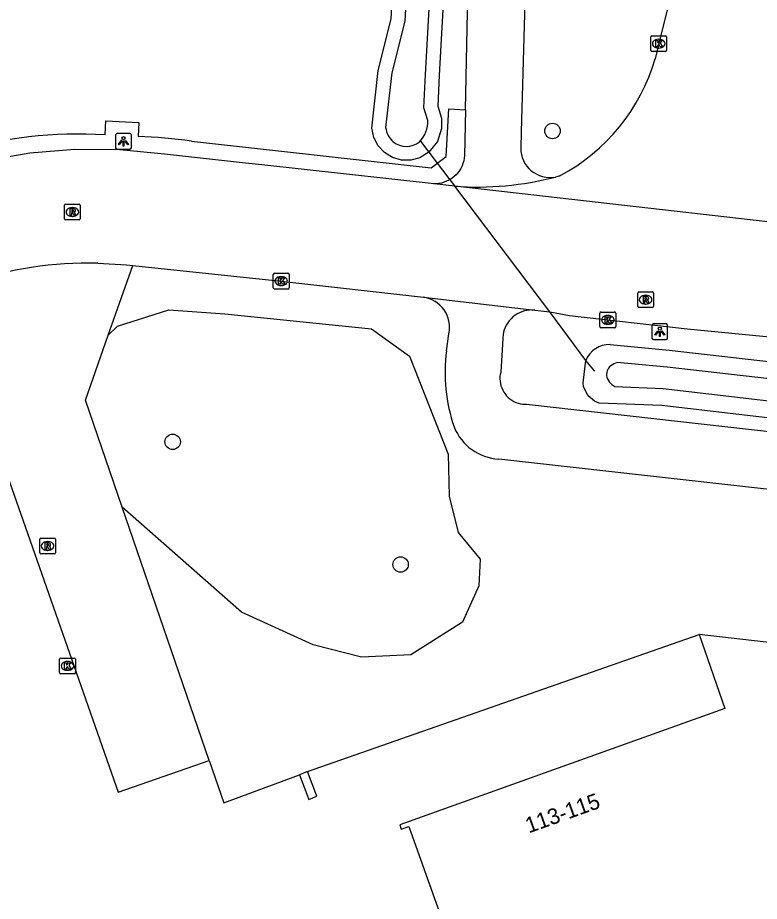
# Model space of a CAD drawing. Extents: x 161389 to 162585, y 388479 to 389761.
# Drawn here: x 162157.9 to 162205, y 388650.1 to 388706.2 of the extents above; entities that cross this region are included whole.
import ezdxf

# ---------------------------------------------------------------- set-up
doc = ezdxf.new("R2010")
doc.units = 0
for name, color, linetype in [('IMGEO_Berm_groen', 7, 'Continuous'), ('IMGEO_Boom', 7, 'Continuous'), ('IMGEO_Duiker', 7, 'Continuous'), ('IMGEO_Fietspad_gesloten', 7, 'Continuous'), ('IMGEO_Groenvoorziening', 7, 'Continuous'), ('IMGEO_Kolk', 7, 'Continuous'), ('IMGEO_Lichtpunt', 7, 'Continuous'), ('IMGEO_Pand', 7, 'Continuous'), ('IMGEO_Pand_nummerreeks', 7, 'Continuous'), ('IMGEO_Rijbaan_lokaal_gesloten', 7, 'Continuous'), ('IMGEO_Rijbaan_lokaal_open', 7, 'Continuous'), ('IMGEO_Rioolput', 7, 'Continuous'), ('IMGEO_Voetpad_open', 7, 'Continuous'), ('IMGEO_Waterloop', 7, 'Continuous')]:
    doc.layers.add(name, color=color, linetype=linetype)

msp = doc.modelspace()

# ---------------------------------------------------------------- linework, layer by layer
at = {"layer": 'IMGEO_Berm_groen'}
for points in [[(162195.511, 388685.399), (162199.258, 388685.044), (162309.372, 388672.493), (162313.677, 388672.019)], [(162314.929, 388670.455), (162314.838, 388669.228), (162314.739, 388669.003), (162314.316, 388668.451), (162313.561, 388668.026), (162313.044, 388667.945), (162308.893, 388668.677), (162198.797, 388681.534), (162194.824, 388681.685), (162194.516, 388681.817), (162194.124, 388682.146), (162193.837, 388682.714), (162193.797, 388682.968), (162193.974, 388684.393)]]:
    msp.add_lwpolyline(points, dxfattribs=at)
msp.add_arc((162195.451, 388683.814), 1.587, 87.8319, 158.5793, dxfattribs=at)
at = {"layer": 'IMGEO_Boom'}
for centre in [(162191.857, 388698.963), (162167.736, 388679.227), (162182.211, 388671.44)]:
    msp.add_circle(centre, 0.489, dxfattribs=at)
at = {"layer": 'IMGEO_Duiker'}
for points in [[(162183.486, 388698.312), (162184.011, 388697.62), (162185.337, 388695.87), (162185.651, 388695.455)], [(162194.552, 388683.711), (162193.974, 388684.393), (162191.691, 388687.487), (162185.651, 388695.455)]]:
    msp.add_lwpolyline(points, dxfattribs=at)
at = {"layer": 'IMGEO_Fietspad_gesloten'}
for points in [[(162186.329, 388700.295), (162186.802, 388723.126), (162187.239, 388731.997), (162188.536, 388741.532), (162190.109, 388750), (162191.97, 388758.076), (162195.928, 388774.095), (162196.55, 388776.78), (162196.93, 388779.509), (162197.064, 388782.261), (162196.952, 388785.015)], [(162190.386, 388722.102), (162190.347, 388716.013), (162190.335, 388715.366), (162189.876, 388698.902), (162189.839, 388697.876)], [(162186.329, 388700.295), (162186.269, 388697.407), (162186.252, 388697.229), (162186.22, 388697.063), (162186.173, 388696.9), (162186.112, 388696.742), (162186.037, 388696.59), (162185.949, 388696.446), (162185.848, 388696.31), (162185.736, 388696.183), (162185.612, 388696.067), (162185.479, 388695.962), (162185.337, 388695.87), (162185.285, 388695.84), (162185.134, 388695.766), (162184.976, 388695.705), (162184.814, 388695.659), (162184.649, 388695.627), (162184.481, 388695.61), (162184.312, 388695.609), (162184.144, 388695.622)], [(162190.731, 388687.591), (162190.565, 388687.6), (162190.4, 388687.594), (162190.235, 388687.573), (162190.073, 388687.537), (162189.915, 388687.488), (162189.762, 388687.424), (162189.615, 388687.347), (162189.476, 388687.257), (162189.345, 388687.155), (162189.224, 388687.041), (162189.113, 388686.918), (162189.014, 388686.785), (162188.927, 388686.643), (162188.854, 388686.495), (162188.794, 388686.34), (162188.747, 388686.181), (162188.716, 388686.018), (162188.699, 388685.853), (162188.696, 388685.79), (162188.57, 388683.655), (162188.54, 388683.511), (162188.523, 388683.366), (162188.52, 388683.219), (162188.529, 388683.073), (162188.552, 388682.928), (162188.587, 388682.786), (162188.635, 388682.647), (162188.695, 388682.513), (162188.766, 388682.385), (162188.849, 388682.265), (162188.943, 388682.151), (162189.046, 388682.047), (162189.158, 388681.953), (162189.278, 388681.868), (162189.405, 388681.795), (162189.538, 388681.734), (162189.676, 388681.684), (162189.818, 388681.647), (162189.962, 388681.623), (162190.109, 388681.612), (162190.209, 388681.612), (162327.081, 388666.21)], [(162185.128, 388685.009), (162185.28, 388686.094)], [(162212.05, 388675.493), (162188.441, 388678.131)]]:
    msp.add_lwpolyline(points, dxfattribs=at)
for centre, radius, start, end in [((162191.706, 388697.876), 1.867, 180.0152, 280.4452), ((162183.403, 388686.501), 1.92, 347.749, 82.4112), ((162195.589, 388683.618), 10.553, 172.4281, 199.0682), ((162188.627, 388681.366), 3.241, 201.6437, 266.7077)]:
    msp.add_arc(centre, radius, start, end, dxfattribs=at)
at = {"layer": 'IMGEO_Groenvoorziening'}
for points in [[(162185.324, 388714.25), (162184.667, 388702.506), (162184.568, 388700.542), (162184.809, 388699.772), (162184.811, 388699.122), (162184.547, 388698.299), (162184.011, 388697.62), (162183.444, 388697.26), (162182.868, 388697.109), (162182.272, 388697.116), (162181.7, 388697.28), (162181.192, 388697.59), (162180.784, 388698.024), (162180.506, 388698.551), (162180.377, 388699.132), (162180.783, 388702.801), (162181.617, 388706.073), (162182.042, 388714.232)], [(162163.648, 388686.001), (162164.223, 388686.562), (162167.504, 388687.618), (162171.048, 388687.354), (162180.363, 388686.411), (162182.776, 388684.676), (162185.228, 388678.454), (162185.303, 388675.776), (162185.869, 388673.476), (162187.264, 388671.779), (162187.189, 388670.082), (162186.133, 388667.782), (162182.852, 388665.708), (162179.722, 388665.557), (162176.667, 388666.349), (162172.104, 388668.423), (162164.533, 388675.08)], [(162176.301, 388658.294), (162201.171, 388666.993)], [(162170.064, 388658.999), (162170.991, 388656.301), (162175.785, 388658.097)]]:
    msp.add_lwpolyline(points, dxfattribs=at)
at = {"layer": 'IMGEO_Kolk'}
for p, q in [((162198.102, 388704.08), (162198.102, 388704.932)), ((162198.177, 388705.006), (162199.029, 388705.006)), ((162198.59, 388704.786), (162198.615, 388704.786)), ((162199.103, 388704.932), (162199.103, 388704.08)), ((162198.613, 388704.226), (162198.588, 388704.226)), ((162199.029, 388704.006), (162198.177, 388704.006)), ((162174.129, 388689.004), (162174.129, 388689.856)), ((162174.204, 388689.93), (162175.056, 388689.93)), ((162174.617, 388689.71), (162174.642, 388689.71)), ((162175.13, 388689.856), (162175.13, 388689.004)), ((162174.64, 388689.15), (162174.615, 388689.15)), ((162175.056, 388688.93), (162174.204, 388688.93)), ((162194.873, 388686.544), (162194.873, 388687.396)), ((162194.948, 388687.47), (162195.8, 388687.47)), ((162195.874, 388687.396), (162195.874, 388686.544)), ((162195.361, 388687.25), (162195.386, 388687.25)), ((162195.8, 388686.47), (162194.948, 388686.47)), ((162195.384, 388686.69), (162195.359, 388686.69)), ((162160.631, 388665.503), (162161.483, 388665.503)), ((162160.556, 388664.577), (162160.556, 388665.429)), ((162161.044, 388665.283), (162161.069, 388665.283)), ((162161.557, 388665.429), (162161.557, 388664.577)), ((162161.483, 388664.503), (162160.631, 388664.503)), ((162161.067, 388664.723), (162161.042, 388664.723))]:
    msp.add_line(p, q, dxfattribs=at)
for points in [[(162198.102, 388704.08), (162198.102, 388704.932)], [(162198.177, 388705.006), (162199.029, 388705.006)], [(162199.103, 388704.932), (162199.103, 388704.08)], [(162198.423, 388704.706), (162198.546, 388704.706), (162198.546, 388704.555), (162198.676, 388704.706), (162198.84, 388704.706), (162198.694, 388704.555), (162198.847, 388704.306), (162198.695, 388704.306), (162198.61, 388704.47), (162198.546, 388704.403), (162198.546, 388704.306), (162198.423, 388704.306), (162198.423, 388704.706)], [(162199.029, 388704.006), (162198.177, 388704.006)], [(162174.129, 388689.004), (162174.129, 388689.856)], [(162174.204, 388689.93), (162175.056, 388689.93)], [(162174.45, 388689.63), (162174.573, 388689.63), (162174.573, 388689.479), (162174.703, 388689.63), (162174.867, 388689.63), (162174.721, 388689.479), (162174.874, 388689.23), (162174.722, 388689.23), (162174.637, 388689.394), (162174.573, 388689.327), (162174.573, 388689.23), (162174.45, 388689.23), (162174.45, 388689.63)], [(162175.13, 388689.856), (162175.13, 388689.004)], [(162175.056, 388688.93), (162174.204, 388688.93)], [(162194.873, 388686.544), (162194.873, 388687.396)], [(162194.948, 388687.47), (162195.8, 388687.47)], [(162195.874, 388687.396), (162195.874, 388686.544)], [(162195.194, 388687.17), (162195.317, 388687.17), (162195.317, 388687.019), (162195.447, 388687.17), (162195.611, 388687.17), (162195.465, 388687.019), (162195.618, 388686.77), (162195.466, 388686.77), (162195.381, 388686.934), (162195.317, 388686.867), (162195.317, 388686.77), (162195.194, 388686.77), (162195.194, 388687.17)], [(162195.8, 388686.47), (162194.948, 388686.47)], [(162160.631, 388665.503), (162161.483, 388665.503)], [(162160.556, 388664.577), (162160.556, 388665.429)], [(162160.877, 388665.203), (162161, 388665.203), (162161, 388665.052), (162161.13, 388665.203), (162161.294, 388665.203), (162161.148, 388665.052), (162161.301, 388664.803), (162161.149, 388664.803), (162161.064, 388664.967), (162161, 388664.9), (162161, 388664.803), (162160.877, 388664.803), (162160.877, 388665.203)], [(162161.557, 388665.429), (162161.557, 388664.577)], [(162161.483, 388664.503), (162160.631, 388664.503)]]:
    msp.add_lwpolyline(points, dxfattribs=at)
for centre, start, end in [((162198.179, 388704.93), 91.552, 178.448), ((162198.179, 388704.93), 91.552, 178.448), ((162199.027, 388704.93), 1.552, 88.448), ((162199.027, 388704.93), 1.552, 88.448), ((162198.179, 388704.082), 181.552, 268.448), ((162198.179, 388704.082), 181.552, 268.448), ((162199.027, 388704.082), 271.552, 358.448), ((162199.027, 388704.082), 271.552, 358.448), ((162174.206, 388689.854), 91.552, 178.448), ((162174.206, 388689.854), 91.552, 178.448), ((162175.054, 388689.854), 1.552, 88.448), ((162175.054, 388689.854), 1.552, 88.448), ((162174.206, 388689.006), 181.552, 268.448), ((162174.206, 388689.006), 181.552, 268.448), ((162175.054, 388689.006), 271.552, 358.448), ((162175.054, 388689.006), 271.552, 358.448), ((162194.95, 388687.394), 91.552, 178.448), ((162194.95, 388687.394), 91.552, 178.448), ((162195.798, 388687.394), 1.552, 88.448), ((162195.798, 388687.394), 1.552, 88.448), ((162194.95, 388686.546), 181.552, 268.448), ((162194.95, 388686.546), 181.552, 268.448), ((162195.798, 388686.546), 271.552, 358.448), ((162195.798, 388686.546), 271.552, 358.448), ((162160.633, 388665.427), 91.552, 178.448), ((162160.633, 388665.427), 91.552, 178.448), ((162161.481, 388665.427), 1.552, 88.448), ((162161.481, 388665.427), 1.552, 88.448), ((162160.633, 388664.579), 181.552, 268.448), ((162160.633, 388664.579), 181.552, 268.448), ((162161.481, 388664.579), 271.552, 358.448), ((162161.481, 388664.579), 271.552, 358.448)]:
    msp.add_arc(centre, 0.0765, start, end, dxfattribs=at)
for centre, major_axis, ratio, start_param, end_param in [((162198.589, 388704.506), (-0.387, 0.002), 0.722429, 4.712389, 7.853982), ((162198.614, 388704.506), (-0.39, 0.002), 0.717154, 1.570796, 4.712389), ((162174.616, 388689.43), (-0.387, 0.002), 0.722429, 4.712389, 7.853982), ((162174.641, 388689.43), (-0.39, 0.002), 0.717154, 1.570796, 4.712389), ((162195.36, 388686.97), (-0.387, 0.002), 0.722429, 4.712389, 7.853982), ((162195.385, 388686.97), (-0.39, 0.002), 0.717154, 1.570796, 4.712389), ((162161.043, 388665.003), (-0.387, 0.002), 0.722429, 4.712389, 7.853982), ((162161.068, 388665.003), (-0.39, 0.002), 0.717154, 1.570796, 4.712389)]:
    msp.add_ellipse(centre, major_axis=major_axis, ratio=ratio, start_param=start_param, end_param=end_param, dxfattribs=at)
at = {"layer": 'IMGEO_Lichtpunt'}
for p, q in [((162164.117, 388698.705), (162164.117, 388697.898)), ((162164.117, 388698.705), (162164.117, 388697.898)), ((162165.019, 388698.8), (162164.211, 388698.8)), ((162165.019, 388698.8), (162164.211, 388698.8)), ((162165.113, 388697.898), (162165.113, 388698.705)), ((162165.113, 388697.898), (162165.113, 388698.705)), ((162164.211, 388697.804), (162165.019, 388697.804)), ((162164.211, 388697.804), (162165.019, 388697.804)), ((162198.176, 388686.618), (162198.176, 388685.811)), ((162198.176, 388686.618), (162198.176, 388685.811)), ((162199.078, 388686.713), (162198.27, 388686.713)), ((162199.078, 388686.713), (162198.27, 388686.713)), ((162199.172, 388685.811), (162199.172, 388686.618)), ((162199.172, 388685.811), (162199.172, 388686.618)), ((162198.27, 388685.717), (162199.078, 388685.717)), ((162198.27, 388685.717), (162199.078, 388685.717))]:
    msp.add_line(p, q, dxfattribs=at)
for points in [[(162164.491, 388698.369), (162164.53, 388698.341), (162164.342, 388698.079), (162164.304, 388698.106), (162164.491, 388698.369)], [(162164.593, 388698.321), (162164.64, 388698.321), (162164.64, 388697.999), (162164.593, 388697.999), (162164.593, 388698.321)], [(162164.703, 388698.341), (162164.741, 388698.368), (162164.928, 388698.106), (162164.889, 388698.078), (162164.703, 388698.341)], [(162198.55, 388686.282), (162198.589, 388686.254), (162198.401, 388685.992), (162198.363, 388686.019), (162198.55, 388686.282)], [(162198.652, 388686.234), (162198.699, 388686.234), (162198.699, 388685.912), (162198.652, 388685.912), (162198.652, 388686.234)], [(162198.762, 388686.254), (162198.8, 388686.281), (162198.987, 388686.019), (162198.948, 388685.991), (162198.762, 388686.254)]]:
    msp.add_lwpolyline(points, dxfattribs=at)
for centre in [(162164.616, 388698.503), (162198.675, 388686.416)]:
    msp.add_circle(centre, 0.0994, dxfattribs=at)
for centre, start, end in [((162164.211, 388698.705), 90, 180), ((162164.211, 388698.705), 90, 180), ((162165.019, 388698.705), 0, 90), ((162165.019, 388698.705), 0, 90), ((162164.211, 388697.898), 180, 270), ((162164.211, 388697.898), 180, 270), ((162165.019, 388697.898), 270, 0), ((162165.019, 388697.898), 270, 360), ((162198.27, 388686.618), 90, 180), ((162198.27, 388686.618), 90, 180), ((162199.078, 388686.618), 0, 90), ((162199.078, 388686.618), 0, 90), ((162198.27, 388685.811), 180, 270), ((162198.27, 388685.811), 180, 270), ((162199.078, 388685.811), 270, 0), ((162199.078, 388685.811), 270, 360)]:
    msp.add_arc(centre, 0.0946, start, end, dxfattribs=at)
at = {"layer": 'IMGEO_Pand'}
for points in [[(162201.171, 388666.993), (162202.802, 388662.297), (162182.158, 388654.923), (162182.252, 388654.637), (162182.743, 388654.798), (162185.543, 388646.914), (162180.831, 388645.223), (162180.558, 388645.977), (162180.164, 388645.887), (162182.655, 388638.891), (162184.222, 388634.491), (162188.677, 388621.975), (162192.555, 388611.083), (162248.797, 388631.105), (162237.455, 388662.849)], [(162211.331, 388665.832), (162201.171, 388666.993)], [(162175.785, 388658.097), (162176.388, 388656.526), (162176.903, 388656.724), (162176.301, 388658.294)], [(162176.301, 388658.294), (162175.785, 388658.097)]]:
    msp.add_lwpolyline(points, dxfattribs=at)
at = {"layer": 'IMGEO_Rijbaan_lokaal_gesloten'}
for points in [[(162218.716, 388784.885), (162218.423, 388783.692), (162213.659, 388764.62), (162209.992, 388750), (162203.693, 388724.874), (162198.604, 388704.506), (162198.376, 388703.539)], [(162184.144, 388695.622), (162173.399, 388696.814), (162172.37, 388696.928), (162167.215, 388697.5), (162164.374, 388697.772), (162161.52, 388697.79), (162158.676, 388697.553), (162155.864, 388697.062), (162153.363, 388696.402), (162146.927, 388694.447), (162132.447, 388689.985), (162128.516, 388688.763)], [(162192.33, 388696.117), (162192.188, 388696.076), (162192.045, 388696.04)], [(162185.651, 388695.455), (162184.144, 388695.622)], [(162216.117, 388691.984), (162185.651, 388695.455)], [(162162.995, 388690.57), (162164.811, 388690.455), (162165.201, 388690.414)], [(162165.201, 388690.414), (162174.63, 388689.431), (162183.657, 388688.405)], [(162183.657, 388688.405), (162190.731, 388687.591)], [(162190.731, 388687.591), (162191.691, 388687.487), (162192.948, 388687.248), (162200.409, 388686.41), (162212.852, 388685.186), (162234.573, 388682.697), (162256.569, 388680.26), (162277.429, 388677.907), (162297.925, 388675.602), (162319.739, 388673.126), (162319.871, 388673.113), (162320.835, 388672.971)]]:
    msp.add_lwpolyline(points, dxfattribs=at)
for centre, radius, start, end in [((162186.575, 388706.979), 12.292, 297.9168, 343.7503), ((162187.072, 388715.159), 19.755, 265.8751, 284.58), ((162162.399, 388666.721), 23.856, 88.5689, 108.8944)]:
    msp.add_arc(centre, radius, start, end, dxfattribs=at)
at = {"layer": 'IMGEO_Rijbaan_lokaal_open'}
for points in [[(162163.648, 388686.001), (162165.201, 388690.414)], [(162164.533, 388675.08), (162162.196, 388681.874), (162163.648, 388686.001)], [(162154.569, 388683.938), (162154.98, 388683.469), (162164.277, 388656.982), (162170.064, 388658.999)], [(162170.064, 388658.999), (162164.533, 388675.08)]]:
    msp.add_lwpolyline(points, dxfattribs=at)
at = {"layer": 'IMGEO_Rioolput'}
for p, q in [((162160.869, 388693.394), (162160.869, 388694.246)), ((162160.944, 388694.32), (162161.796, 388694.32)), ((162161.357, 388694.1), (162161.382, 388694.1)), ((162161.87, 388694.246), (162161.87, 388693.394)), ((162161.38, 388693.54), (162161.355, 388693.54)), ((162161.796, 388693.32), (162160.944, 388693.32)), ((162197.271, 388687.824), (162197.271, 388688.676)), ((162197.346, 388688.75), (162198.198, 388688.75)), ((162197.759, 388688.53), (162197.784, 388688.53)), ((162198.272, 388688.676), (162198.272, 388687.824)), ((162197.782, 388687.97), (162197.757, 388687.97)), ((162198.198, 388687.75), (162197.346, 388687.75)), ((162159.291, 388672.19), (162159.291, 388673.042)), ((162159.366, 388673.116), (162160.218, 388673.116)), ((162159.779, 388672.896), (162159.804, 388672.896)), ((162160.292, 388673.042), (162160.292, 388672.19)), ((162159.802, 388672.336), (162159.777, 388672.336)), ((162160.218, 388672.116), (162159.366, 388672.116))]:
    msp.add_line(p, q, dxfattribs=at)
for points in [[(162160.869, 388693.394), (162160.869, 388694.246)], [(162160.944, 388694.32), (162161.796, 388694.32)], [(162161.87, 388694.246), (162161.87, 388693.394)], [(162161.458, 388694.018), (162161.206, 388694.02), (162161.206, 388693.62)], [(162161.206, 388693.62), (162161.33, 388693.62), (162161.33, 388693.782), (162161.341, 388693.782)], [(162161.384, 388693.939), (162161.33, 388693.939), (162161.33, 388693.858)], [(162161.33, 388693.858), (162161.382, 388693.858)], [(162161.388, 388693.753), (162161.459, 388693.62), (162161.599, 388693.62), (162161.534, 388693.746)], [(162161.796, 388693.32), (162160.944, 388693.32)], [(162197.271, 388687.824), (162197.271, 388688.676)], [(162197.346, 388688.75), (162198.198, 388688.75)], [(162198.272, 388688.676), (162198.272, 388687.824)], [(162197.86, 388688.448), (162197.608, 388688.45), (162197.608, 388688.05)], [(162197.608, 388688.05), (162197.732, 388688.05), (162197.732, 388688.212), (162197.743, 388688.212)], [(162197.786, 388688.369), (162197.732, 388688.369), (162197.732, 388688.288)], [(162197.732, 388688.288), (162197.784, 388688.288)], [(162197.79, 388688.183), (162197.861, 388688.05), (162198.001, 388688.05), (162197.936, 388688.176)], [(162198.198, 388687.75), (162197.346, 388687.75)], [(162159.291, 388672.19), (162159.291, 388673.042)], [(162159.366, 388673.116), (162160.218, 388673.116)], [(162159.88, 388672.814), (162159.628, 388672.816), (162159.628, 388672.416)], [(162160.292, 388673.042), (162160.292, 388672.19)], [(162159.628, 388672.416), (162159.752, 388672.416), (162159.752, 388672.578), (162159.763, 388672.578)], [(162159.806, 388672.735), (162159.752, 388672.735), (162159.752, 388672.654)], [(162159.752, 388672.654), (162159.804, 388672.654)], [(162159.81, 388672.549), (162159.881, 388672.416), (162160.021, 388672.416), (162159.956, 388672.542)], [(162160.218, 388672.116), (162159.366, 388672.116)]]:
    msp.add_lwpolyline(points, dxfattribs=at)
for centre, radius, start, end in [((162160.946, 388694.244), 0.0765, 91.552, 178.448), ((162160.946, 388694.244), 0.0765, 91.552, 178.448), ((162161.794, 388694.244), 0.0765, 1.552, 88.448), ((162161.794, 388694.244), 0.0765, 1.552, 88.448), ((162161.34, 388693.729), 0.0533, 26.0293, 88.6989), ((162161.366, 388694.047), 0.19, 274.7715, 282.9687), ((162161.39, 388693.843), 0.0964, 77.0061, 93.1865), ((162161.404, 388693.9), 0.0378, 276.6634, 79.6772), ((162161.457, 388693.908), 0.109, 350.3612, 89.416), ((162161.455, 388693.908), 0.112, 277.5842, 350.9817), ((162161.439, 388693.693), 0.108, 29.5134, 73.7905), ((162160.946, 388693.396), 0.0765, 181.552, 268.448), ((162160.946, 388693.396), 0.0765, 181.552, 268.448), ((162161.794, 388693.396), 0.0765, 271.552, 358.448), ((162161.794, 388693.396), 0.0765, 271.552, 358.448), ((162197.348, 388688.674), 0.0765, 91.552, 178.448), ((162197.348, 388688.674), 0.0765, 91.552, 178.448), ((162198.196, 388688.674), 0.0765, 1.552, 88.448), ((162198.196, 388688.674), 0.0765, 1.552, 88.448), ((162197.742, 388688.159), 0.0533, 26.0293, 88.6989), ((162197.768, 388688.477), 0.19, 274.7715, 282.9687), ((162197.792, 388688.273), 0.0964, 77.0061, 93.1865), ((162197.806, 388688.33), 0.0378, 276.6634, 79.6772), ((162197.859, 388688.338), 0.109, 350.3612, 89.416), ((162197.857, 388688.338), 0.112, 277.5842, 350.9817), ((162197.841, 388688.123), 0.108, 29.5134, 73.7905), ((162197.348, 388687.826), 0.0765, 181.552, 268.448), ((162197.348, 388687.826), 0.0765, 181.552, 268.448), ((162198.196, 388687.826), 0.0765, 271.552, 358.448), ((162198.196, 388687.826), 0.0765, 271.552, 358.448), ((162159.368, 388673.04), 0.0765, 91.552, 178.448), ((162159.368, 388673.04), 0.0765, 91.552, 178.448), ((162159.879, 388672.704), 0.109, 350.3612, 89.416), ((162160.216, 388673.04), 0.0765, 1.552, 88.448), ((162160.216, 388673.04), 0.0765, 1.552, 88.448), ((162159.368, 388672.192), 0.0765, 181.552, 268.448), ((162159.368, 388672.192), 0.0765, 181.552, 268.448), ((162159.762, 388672.525), 0.0533, 26.0293, 88.6989), ((162159.788, 388672.843), 0.19, 274.7715, 282.9687), ((162159.812, 388672.639), 0.0964, 77.0061, 93.1865), ((162159.826, 388672.696), 0.0378, 276.6634, 79.6772), ((162159.877, 388672.704), 0.112, 277.5842, 350.9817), ((162159.861, 388672.489), 0.108, 29.5134, 73.7905), ((162160.216, 388672.192), 0.0765, 271.552, 358.448), ((162160.216, 388672.192), 0.0765, 271.552, 358.448)]:
    msp.add_arc(centre, radius, start, end, dxfattribs=at)
for centre, major_axis, ratio, start_param, end_param in [((162161.356, 388693.82), (-0.387, 0.002), 0.722429, 4.712389, 7.853982), ((162161.381, 388693.82), (-0.39, 0.002), 0.717154, 1.570796, 4.712389), ((162197.758, 388688.25), (-0.387, 0.002), 0.722429, 4.712389, 7.853982), ((162197.783, 388688.25), (-0.39, 0.002), 0.717154, 1.570796, 4.712389), ((162159.778, 388672.616), (-0.387, 0.002), 0.722429, 4.712389, 7.853982), ((162159.803, 388672.616), (-0.39, 0.002), 0.717154, 1.570796, 4.712389)]:
    msp.add_ellipse(centre, major_axis=major_axis, ratio=ratio, start_param=start_param, end_param=end_param, dxfattribs=at)
at = {"layer": 'IMGEO_Voetpad_open'}
for points in [[(162168.937, 388698.323), (162184.152, 388696.632), (162185.097, 388697.352), (162185.266, 388700.364), (162186.329, 388700.295)], [(162163.455, 388698.718), (162163.501, 388699.614), (162165.591, 388699.502), (162165.54, 388698.604)]]:
    msp.add_lwpolyline(points, dxfattribs=at)
for centre, radius, start, end in [((162161.799, 388669.856), 28.91, 86.7155, 106.0041), ((162164.47, 388664.997), 33.624, 82.3658, 88.1767)]:
    msp.add_arc(centre, radius, start, end, dxfattribs=at)
at = {"layer": 'IMGEO_Waterloop'}
for points in [[(162183.935, 388699.637), (162183.687, 388700.43), (162183.794, 388702.552), (162184.455, 388714.365), (162185.037, 388717.142), (162184.552, 388723.272), (162185.295, 388735.972), (162187.332, 388750.153), (162188.703, 388756.652), (162192.714, 388770.941), (162187.655, 388784.885), (162184.725, 388787.123), (162183.897, 388787.97), (162183.246, 388788.961), (162183.097, 388789.284)], [(162190.647, 388766.58), (162187.528, 388755.811), (162186.078, 388749.795), (162185.299, 388746.561), (162183.314, 388730.079), (162182.916, 388714.198), (162182.486, 388705.941), (162181.646, 388702.644), (162181.262, 388699.18)], [(162195.97, 388684.262), (162195.754, 388684.173), (162195.481, 388683.991)], [(162312.727, 388671.029), (162309.251, 388671.412), (162199.145, 388683.962), (162195.97, 388684.262)], [(162195.347, 388683.225), (162195.481, 388683.01), (162195.633, 388682.868), (162195.82, 388682.736), (162198.881, 388682.62), (162309.051, 388669.754), (162312.207, 388669.198)]]:
    msp.add_lwpolyline(points, dxfattribs=at)
for centre, radius, start, end in [((162182.726, 388699.383), 1.478, 187.9018, 228.5713), ((162182.19, 388699.525), 1.749, 314.5649, 3.6771), ((162182.58, 388699.308), 1.326, 231.1532, 309.1215), ((162196.019, 388683.502), 0.727, 137.7209, 202.4339)]:
    msp.add_arc(centre, radius, start, end, dxfattribs=at)

# ---------------------------------------------------------------- texts
at = {"layer": 'IMGEO_Pand_nummerreeks'}
msp.add_text('113-115', height=1, rotation=19.658, dxfattribs=at).set_placement((162190.349, 388654.366))

doc.saveas('drawing.dxf')
